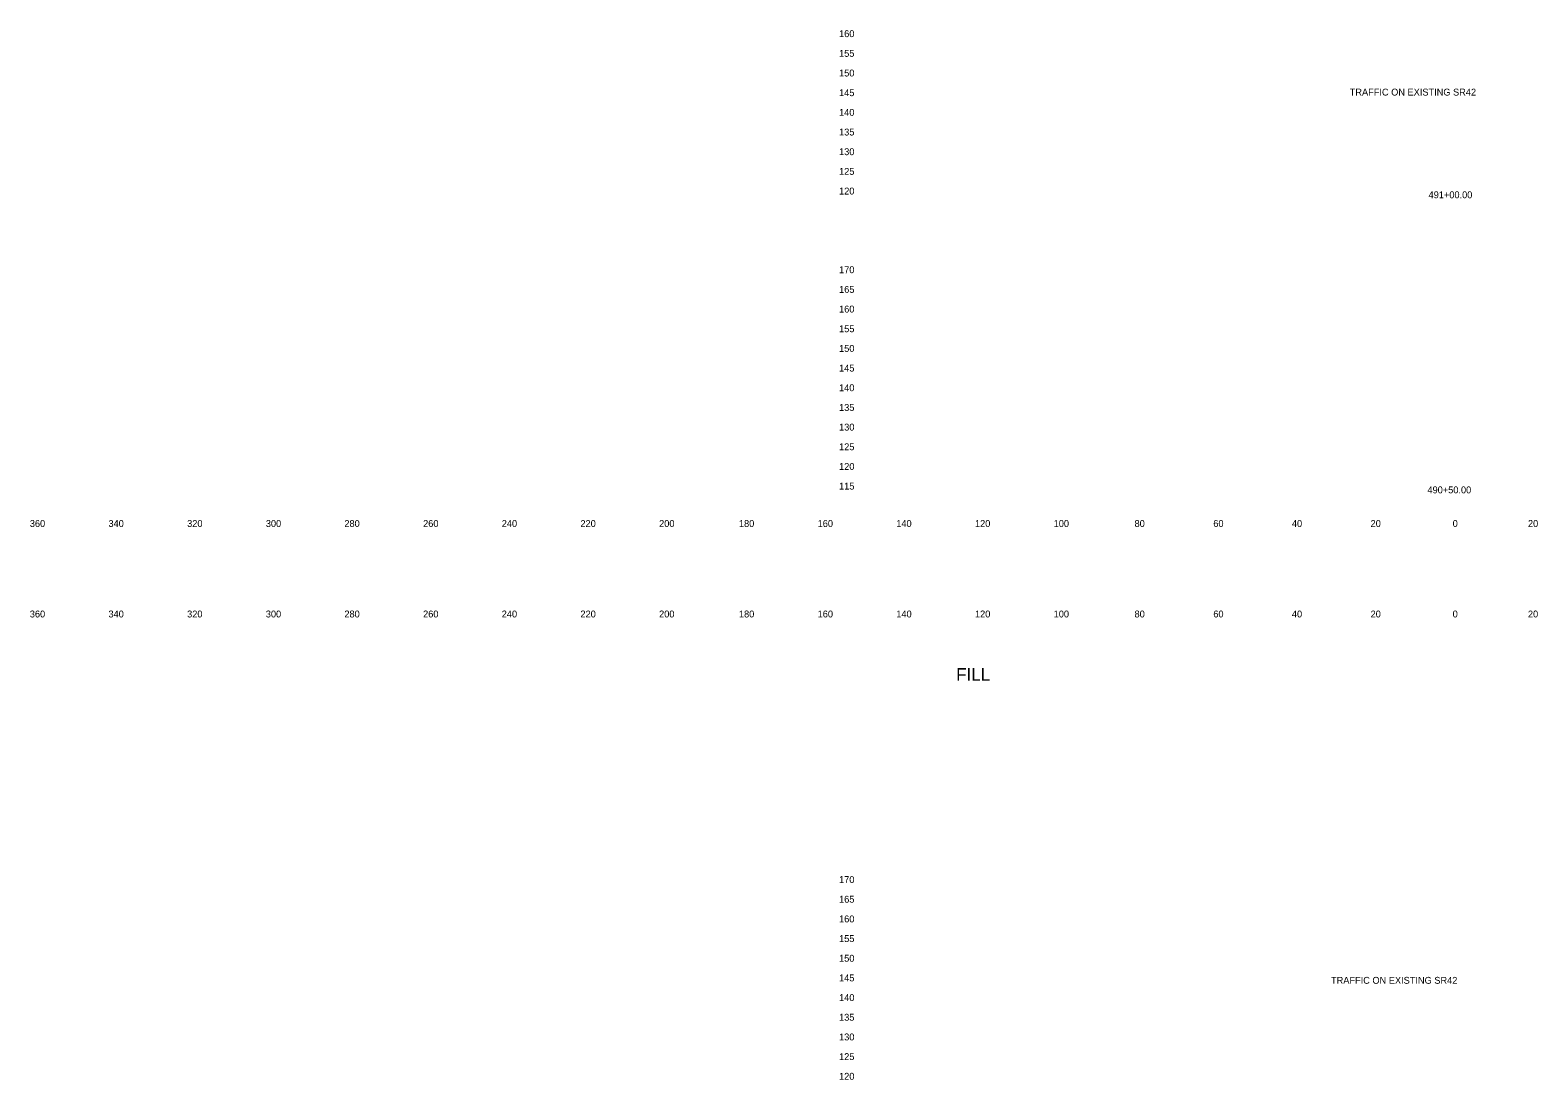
# Model space of a CAD drawing. Extents: x 21281 to 22024, y 6472 to 15198.
# Drawn here: x 21280.5 to 21663.8, y 14384.8 to 14651.6 of the extents above; entities that cross this region are included whole.
import ezdxf

# ---------------------------------------------------------------- set-up
doc = ezdxf.new("R2010")
doc.units = 0
for name, color, linetype in [('XS_SHEET_LABELS_ELEVATION', 7, 'Continuous'), ('XS_SHEET_LABELS_OFFSET', 7, 'Continuous'), ('XS_SHEET_LABELS_STATION', 7, 'Continuous')]:
    doc.layers.add(name, color=color, linetype=linetype)

msp = doc.modelspace()

# ---------------------------------------------------------------- texts
at = {"layer": 'XS_SHEET_LABELS_ELEVATION'}
for s, p in [('  160  ', (21484.84, 14649.84)), ('  155  ', (21484.84, 14644.84)), ('  150  ', (21484.84, 14639.84)), ('  145  ', (21484.84, 14634.84)), ('  140  ', (21484.84, 14629.84)), ('  135  ', (21484.84, 14624.84)), ('  130  ', (21484.84, 14619.84)), ('  125  ', (21484.84, 14614.84)), ('  120  ', (21484.84, 14609.84)), ('  170  ', (21484.84, 14589.84)), ('  165  ', (21484.84, 14584.84)), ('  160  ', (21484.84, 14579.84)), ('  155  ', (21484.84, 14574.84)), ('  150  ', (21484.84, 14569.84)), ('  145  ', (21484.84, 14564.84)), ('  140  ', (21484.84, 14559.84)), ('  135  ', (21484.84, 14554.84)), ('  130  ', (21484.84, 14549.84)), ('  125  ', (21484.84, 14544.84)), ('  120  ', (21484.84, 14539.84)), ('  115  ', (21484.84, 14534.84)), ('  170  ', (21484.84, 14434.84)), ('  165  ', (21484.84, 14429.84)), ('  160  ', (21484.84, 14424.84)), ('  155  ', (21484.84, 14419.84)), ('  150  ', (21484.84, 14414.84)), ('  145  ', (21484.84, 14409.84)), ('  140  ', (21484.84, 14404.84)), ('  135  ', (21484.84, 14399.84)), ('  130  ', (21484.84, 14394.84)), ('  125  ', (21484.84, 14389.84)), ('  120  ', (21484.84, 14384.84))]:
    msp.add_text(s, height=1.75, dxfattribs=at).set_placement(p)
at = {"layer": 'XS_SHEET_LABELS_OFFSET'}
for s, height, p in [('  360  ', 1.75, (21279.14, 14525.34)), ('  340  ', 1.75, (21299.13, 14525.34)), ('  320  ', 1.75, (21319.13, 14525.34)), ('  300  ', 1.75, (21339.13, 14525.34)), ('  280  ', 1.75, (21359.1, 14525.34)), ('  260  ', 1.75, (21379.11, 14525.34)), ('  240  ', 1.75, (21399.1, 14525.34)), ('  220  ', 1.75, (21419.1, 14525.34)), ('  200  ', 1.75, (21439.1, 14525.34)), ('  180  ', 1.75, (21459.39, 14525.34)), ('  160  ', 1.75, (21479.4, 14525.34)), ('  140  ', 1.75, (21499.39, 14525.34)), ('  120  ', 1.75, (21519.39, 14525.34)), ('  100  ', 1.75, (21539.39, 14525.34)), ('  80  ', 1.75, (21559.95, 14525.34)), ('  60  ', 1.75, (21579.97, 14525.34)), ('  40  ', 1.75, (21599.95, 14525.34)), ('  20  ', 1.75, (21619.95, 14525.34)), ('  0  ', 1.75, (21640.81, 14525.34)), ('  0  ', 1.75, (21640.81, 14525.34)), ('  20  ', 1.75, (21659.95, 14525.34)), ('  360  ', 1.75, (21279.14, 14502.34)), ('  340  ', 1.75, (21299.13, 14502.34)), ('  320  ', 1.75, (21319.13, 14502.34)), ('  300  ', 1.75, (21339.13, 14502.34)), ('  280  ', 1.75, (21359.1, 14502.34)), ('  260  ', 1.75, (21379.11, 14502.34)), ('  240  ', 1.75, (21399.1, 14502.34)), ('  220  ', 1.75, (21419.1, 14502.34)), ('  200  ', 1.75, (21439.1, 14502.34)), ('  180  ', 1.75, (21459.39, 14502.34)), ('  160  ', 1.75, (21479.4, 14502.34)), ('  140  ', 1.75, (21499.39, 14502.34)), ('  120  ', 1.75, (21519.39, 14502.34)), ('  100  ', 1.75, (21539.39, 14502.34)), ('  80  ', 1.75, (21559.95, 14502.34)), ('  60  ', 1.75, (21579.97, 14502.34)), ('  40  ', 1.75, (21599.95, 14502.34)), ('  20  ', 1.75, (21619.95, 14502.34)), ('  0  ', 1.75, (21640.81, 14502.34)), ('  0  ', 1.75, (21640.81, 14502.34)), ('  20  ', 1.75, (21659.95, 14502.34)), ('FILL', 3.222, (21515.91, 14486.23))]:
    msp.add_text(s, height=height, dxfattribs=at).set_placement(p)
at = {"layer": 'XS_SHEET_LABELS_STATION'}
for s, p in [('TRAFFIC ON EXISTING SR42', (21615.95, 14634.99)), ('  491+00.00  ', (21634.69, 14608.89)), ('  490+50.00  ', (21634.4, 14533.89)), ('TRAFFIC ON EXISTING SR42', (21611.19, 14409.23))]:
    msp.add_text(s, height=1.75, dxfattribs=at).set_placement(p)

doc.saveas('drawing.dxf')
